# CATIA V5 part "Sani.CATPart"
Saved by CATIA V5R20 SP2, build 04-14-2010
Part number: Part2
Bounding box of the stored display mesh (mm): x -33 to 33, y -27.548 to 27.548, z -2.11 to 12
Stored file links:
  C:\Documents and Settings\Administrator\My Documents\Hobi_dokumenti\CAD_CNC\Clap_CATIA\Sani.CATPart
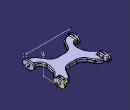
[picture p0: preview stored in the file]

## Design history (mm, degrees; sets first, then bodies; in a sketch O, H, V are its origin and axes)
Set1
  Point1: type Center, Curve edge [face of Mirror3 | face of Mirror3]
  Point2: type Center, Curve edge [face of Mirror2 | face of Mirror3]
  Point3: type Center, Curve edge [face of Mirror3 | face of Mirror3]
  Point4: type Center, Curve edge [face of Mirror8 | face of Mirror8]
  Point5: type Center, Curve edge [face of Mirror8 | face of Mirror8]
  Line1: type PtDir, RefPoint Sketch9, Direction Line2, Start 0, End 60
  Line2: stored without definition
Body1 (main body)
  Sketch1 on xy-plane, origin (0, 0, 0), H (1, 0, 0), V (0, 1, 0)
    line L1 (-30, 25) -> (30, 25)
    line L2 (30, 25) -> (30, -25)
    line L3 (30, -25) -> (-30, -25)
    line L4 (-30, -25) -> (-30, 25)
    reference intersected line E2 through (0, 0) direction (0, 1) from yz-plane
    reference intersected line E3 through (0, 0) direction (-1, 0) from zx-plane
    distance E3 L3 = 25
    distance E3 L1 = 25
    distance E2 L2 = 30
    distance E2 L4 = 30
    horizontal: L1 H, L3 H, E3 H
    vertical: L2 V, L4 V, E2 V
    perpendicularity: E2 L1
  Pad1: profile Sketch1, direction (0, 0, 1), length 5
  Sketch2 on start face of Pad1, origin (0, 0, 0), H (1, 0, 0), V (0, -1, 0)
    offset line E1 (20, 25) -> (20, -25) from edge [start face of Pad1 | face of Pad1 from Sketch1.L2]
    offset line E2 (20, 7) -> (20, 5) from edge [start face of Pad1 | face of Pad1 from Sketch1.L2]
    point P1 (20, 25)
    point P2 (20, -25)
    offset line E3 (-20, -25) -> (-20, 25) from edge [start face of Pad1 | face of Pad1 from Sketch1.L4]
    offset line E4 (-20, 5) -> (-20, 7) from edge [start face of Pad1 | face of Pad1 from Sketch1.L4]
    point P3 (-20, -25)
    point P4 (-20, 25)
    offset line E5 (-30, 15) -> (30, 15) from edge [start face of Pad1 | face of Pad1 from Sketch1.L3]
    offset line E6 (-30, 15) -> (-28, 15) from edge [start face of Pad1 | face of Pad1 from Sketch1.L3]
    offset line E7 (28, 15) -> (30, 15) from edge [start face of Pad1 | face of Pad1 from Sketch1.L3]
    point P5 (-30, 15)
    point P6 (30, 15)
    offset line E8 (30, -15) -> (-30, -15) from edge [start face of Pad1 | face of Pad1 from Sketch1.L1]
    point P7 (30, -15)
    point P8 (-30, -15)
    arc A1 centre (-28, 7) radius 8 from (-28, 15) to (-20, 7) cw
    arc A2 centre (-40, 5) radius 20 from (-20, 5) to (-30, -12.3205) cw
    arc A3 centre (28, 7) radius 8 from (28, 15) to (20, 7) ccw
    arc A4 centre (40, 5) radius 20 from (20, 5) to (30, -12.3205) ccw
    line L1 (30, -12.3205) -> (30, 15)
    line L2 (-30, -12.3205) -> (-30, 15)
    radius A1 = 8
    radius A2 = 20
    radius A3 = 8
    radius A4 = 20
    coincidence: E5 P6, E3 P4, E3 P3, E8 P7, E5 P5, E1 P1, E1 P2, E8 P8
    tangency: A1 E5, A1 E3, A2 E3, A2 E8, A3 E5, A3 E1, A4 E1, A4 E8
    vertical: L1 V, L2 V
  Pocket1: profile Sketch2, direction (0, 0, 1), length 5
  Sketch3 on start face of Pad1, origin (0, 0, 0), H (1, 0, 0), V (0, -1, 0)
    offset line E1 (30, -8) -> (-30, -8) from edge [start face of Pad1 | face of Pad1 from Sketch1.L1]
    point P2 (-30, -8)
    line L1 (-20, -25) -> (-13.0718, -13)
    point P3 (-10.185, -8)
    point P4 (-20, -25)
    reference projected line E2 (-30, -25) -> (-30, 25) from edge [start face of Pad1 | face of Pad1 from Sketch1.L4]
    reference projected line E3 (30, -25) -> (-30, -25) from edge [start face of Pad1 | face of Pad1 from Sketch1.L1]
    reference projected line E4 (30, -25) -> (-30, -25) from edge [start face of Pad1 | face of Pad1 from Sketch1.L1]
    arc A1 centre (-4.4115, -18) radius 10 from (-4.4115, -8) to (-13.0718, -13) ccw
    point P5 (-4.4115, -8)
    point P6 (-13.0718, -13)
    point P8 (10.185, -8)
    point P9 (20, -25)
    point P10 (13.0718, -13)
    point P12 (4.4115, -8)
    line L2 (20, -25) -> (13.0718, -13)
    arc A2 centre (4.4115, -18) radius 10 from (4.4115, -8) to (13.0718, -13) cw
    line L3 (-20, -25) -> (20, -25)
    line L4 (-4.4115, -8) -> (4.4115, -8)
    point P13 (-10.185, 8)
    point P14 (-20, 25)
    point P15 (-4.4115, 8)
    point P16 (-13.0718, 13)
    point P18 (10.185, 8)
    point P19 (20, 25)
    point P20 (13.0718, 13)
    point P22 (4.4115, 8)
    line L5 (-20, 25) -> (-13.0718, 13)
    arc A3 centre (-4.4115, 18) radius 10 from (-4.4115, 8) to (-13.0718, 13) cw
    line L6 (20, 25) -> (13.0718, 13)
    arc A4 centre (4.4115, 18) radius 10 from (4.4115, 8) to (13.0718, 13) ccw
    line L7 (-20, 25) -> (20, 25)
    line L8 (-4.4115, 8) -> (4.4115, 8)
    distance E2 P4 = 10
    distance P4 E3 = 0
    angle E4 L1 = 60
    radius A1 = 10
    coincidence: P3 E1, E1 P2, L1 P3
    tangency: A1 E1, A1 L1, L4 A1
    symmetry: P3 P8 V, P4 P9 V, P6 P10 V, P5 P12 V, L1 L2 V, A1 A2 V, P3 P13 H, P4 P14 H, P5 P15 H, P6 P16 H, P8 P18 H, P9 P19 H, P10 P20 H, P12 P22 H, L1 L5 H, A1 A3 H, L2 L6 H, A2 A4 H, L3 L7 H, L4 L8 H
    horizontal: L3 H
  Pocket2: profile Sketch3, direction (0, 0, 1), length 5
  Fillet1: radius 10, on edge [face of Pocket2 from Sketch3.L5 | face of Pad1 from Sketch1.L3]; edge [face of Pad1 from Sketch1.L1 | face of Pocket2 from Sketch3.L1]; edge [face of Pad1 from Sketch1.L3 | face of Pocket2 from Sketch3.L6]; edge [face of Pocket2 from Sketch3.L2 | face of Pad1 from Sketch1.L1]
  Sketch4 on face of Pad1 from Sketch1.L4, origin (-30, 0, 0), H (0, -1, 0), V (0, 0, 1)
    circle A1 centre (-20, 2.5) radius 2
    point P1 (-20, 2.5)
    radius A1 = 2
    distance H P1 = 2.5
    distance V P1 = 20
  Pad2: profile Sketch4, direction (-1, 0, 0), length 3
  Mirror1: of Pad2, Sketch4, about yz-plane
  Mirror2: of Pad2, Sketch4, about zx-plane
  Mirror3: of the body so far, about yz-plane
  Sketch5 on face of Mirror3, origin (-33, 20, 2.5), H (0, 1, 0), V (0, 0, -1)
    point P1 (0, 0)
  Hole1: placed by Sketch5, at (-33, 20, 2.5) direction (1, 0, 0), diameter 2.4, through (limit type 6), threaded, thread diameter 3, thread depth 10, pitch 0.5
  Mirror4: of Hole1, about zx-plane
  Mirror5: of Hole1, about yz-plane
  Sketch6 on face of Mirror3, origin (33, -20, 2.5), H (0, 1, 0), V (0, 0, 1)
    point P1 (0, 0)
  Hole2: placed by Sketch6, at (33, -20, 2.5) direction (-1, 0, 0), diameter 2.4, through (limit type 6), threaded, thread diameter 3, thread depth 10, pitch 0.5
  Chamfer1: length 1, angle 45, on edge [face of Mirror3 | face of Mirror3] (x12)
  Sketch7 on face of Mirror3, origin (30, 0, 0), H (0, 1, 0), V (0, 0, 1)
    circle A1 centre (20, 2.5) radius 2
    point P1 (20, 2.5)
    ellipse A2 centre (20, 2.5) semi-axes 7.5477, 4.6108 rotation 0
    radius A1 = 2
    distance P1 H = 2.5
    distance P1 V = 20
    "Radius" A2 = 7.5477
    "Radius" A2 = 4.6108
  Pad3: profile Sketch7, direction (-1, 0, 0), length 2
  Mirror6: of Pad3, Sketch7, about zx-plane
  Mirror7: of Pad3, Sketch7, about yz-plane
  Mirror8: of the body so far, about yz-plane
  Fillet2: radius 1.1, on edge [face of Mirror8 | face of Mirror8] (x17); edge [face of Mirror6 | face of Mirror8] (x3); edge [face of Mirror8 | face of Mirror6] (x5)
  Sketch8 on face of Mirror8, origin (0, 0, 5), H (1, 0, 0), V (0, 1, 0)
    point P1 (-26.9, 26)
    line L1 (-26.9, 26) -> (-23.1, 26)
    line L2 (-23.1, 26) -> (-23.1, 14)
    line L3 (-23.1, 14) -> (-26.9, 14)
    line L4 (-26.9, 14) -> (-26.9, 26)
    point P2 (-23.1, 26)
    point P3 (-23.1, 14)
    point P4 (-26.9, 14)
    point P5 (26.9, 26)
    point P6 (23.1, 26)
    point P7 (23.1, 14)
    point P8 (26.9, 14)
    line L5 (26.9, 26) -> (23.1, 26)
    line L6 (23.1, 26) -> (23.1, 14)
    line L7 (23.1, 14) -> (26.9, 14)
    line L8 (26.9, 14) -> (26.9, 26)
    length L1 = 3.8
    length L2 = 12
    distance H L3 = 14
    distance V L2 = 23.1
    horizontal: L1 H, L3 H
    vertical: L2 V, L4 V
    symmetry: P1 P5 V, P2 P6 V, P3 P7 V, P4 P8 V, L1 L5 V, L2 L6 V, L3 L7 V, L4 L8 V
  Pocket3: profile Sketch8, direction (0, 0, -1), length 23
  Fillet3: radius 1.1, on edge [face of Pocket3 from Sketch8.L3 | face of Pocket3 from Sketch8.L4]; edge [face of Pocket3 from Sketch8.L2 | face of Pocket3 from Sketch8.L3]; edge [face of Pocket3 from Sketch8.L7 | face of Pocket3 from Sketch8.L6]; edge [face of Pocket3 from Sketch8.L8 | face of Pocket3 from Sketch8.L7]
  Mirror9: of the body so far, about yz-plane
  Sketch9 on face of Mirror6, origin (30, 0, 0), H (0, 1, 0), V (0, 0, 1)
    point P1 (-24, 12)
    distance P1 V = 24
    distance H P1 = 12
